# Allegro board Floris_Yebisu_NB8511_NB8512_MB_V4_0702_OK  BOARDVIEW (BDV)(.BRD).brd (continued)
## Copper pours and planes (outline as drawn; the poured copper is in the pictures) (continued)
+VCCSFR_OC on ART03: 61.36,76.32 56.29,76.32 56.23,76.26 55.01,76.26 54.63,75.87 52.81,75.87 52.81,75.87 52.34,75.87 52.33,75.86 50.38,75.86 50.24,75.71 50.24,74.7 50.41,74.53 52.9,74.53 52.92,74.55 56.26,74.55 57.05,75.35 61.35,75.35 61.62,75.61 61.62,76.07
+VCCSFR_OC on PWR04: 61.21,76.3 62.34,76.3 64.07,74.58 72.14,74.58 78.54,68.18 80.69,68.18 81.48,67.39 81.48,60.11 81.21,59.85 78.47,59.85 78.07,60.25 78.07,63.5 76.43,65.14 69.31,65.14 60.75,73.69 60.75,75.84
+VCCSFR_OC on ART05: 44.7,71.7 43.64,71.7 43.38,71.45 43.38,70.38 43.64,70.13 46.84,70.13 51.26,74.55 51.26,75.56 51.05,75.77 48.77,75.77
+VCCST on TOP: 108.51,36.35 107.96,36.35 107.68,36.07 107.68,33.76 103.35,29.43 88.17,29.43 86.48,27.73 82.27,27.73 81.35,26.81 81.35,26.44 81.39,26.39 86.67,26.39 88.82,28.54 104.36,28.54 104.8,28.98 105.56,28.98 105.66,28.88 105.66,28.17 105.81,28.01 105.81,27.45 105.87,27.4 107.19,27.4 107.34,27.56 107.34,28.37 107.69,28.72 108.41,28.72 108.46,28.67 108.46,28.27 108.51,28.22 108.81,28.22 108.86,28.27 108.86,30.1 108.8,30.16 108.8,36.06
+VCCST on BOTTOM: 108.71,35.94 109.11,35.54 109.11,34.47 109.01,34.37 109.01,34.36 108.22,34.36 108.01,34.57 108.01,36.11 108.2,36.29 108.46,36.29 108.61,36.14 108.61,36.04 108.71,35.94
+VCCST on BOTTOM: 51.26,66.37 51.26,65.86 51.76,65.35 52.12,65.35 52.22,65.45 52.22,66.34 52.14,66.42 51.66,66.42 51.61,66.47 51.36,66.47
+VCCST on ART05: 82.42,24.84 81.79,24.2 72.64,24.2 72.26,24.58 72.26,25.22 74.17,27.12 82.29,27.12 82.42,27
+VCCST on ART05: 52.68,66.27 52.68,63.47 50.75,61.54 49.73,61.54 49.43,61.85 49.43,63.22 49.63,63.42 49.63,63.93 49.62,63.94 49.62,64.6 51.74,66.72 52.22,66.72
+VCCSTG_IO on BOTTOM: 60.33,36.8 62.85,34.29 75.67,34.29 77.39,32.56 81.56,32.56 84.53,35.53 84.53,36.34 84.68,36.5 84.68,38.81 83.69,39.8 83.69,40.56 82.56,41.69 82.56,42.31 82.61,42.36 82.97,42.36 83.01,42.32 83.01,42 84.35,40.67 84.35,40.26 85.26,39.34 85.26,34.31 82.1,31.15 77.33,31.15 75.13,33.36 61.97,33.36 59.18,36.14 59.18,36.5 59.48,36.8
+VCCSTG_OUT_FUSE on TOP: 106.81,58.19 107.45,58.19 107.45,58.19 107.88,58.19 108.18,57.89 108.18,57.69 108.27,57.6 109.26,57.6 109.29,57.63 109.29,57.98 109.1,58.17 108.73,58.17 108.15,58.75 106.81,58.75
+VDD on TOP: 147.49,63.95 148.13,64.59 148.89,64.59 148.99,64.69 148.99,65.05 148.94,65.1 146.18,65.1 145.97,65.3 145.29,65.3 145.01,65.58 144.42,65.58 144.37,65.53 144.37,64.06 144.48,63.95
+VDDQ_CPU on TOP: 101.51,59.08 104.25,59.08 104.74,59.57 105.13,59.57 105.26,59.45 105.46,59.45 105.95,59.93 109.52,59.93 109.68,59.78 110.42,59.78 110.48,59.84 110.48,60.31 110.05,60.74 110.05,66.32 111.16,67.42 111.16,71.79 111.12,71.83 111.12,74.88 111,75 84.96,75 81.02,71.07 81.02,67.38 81.04,67.37 81.04,60.2 81.04,60.2 81.04,59.74 81.12,59.66 84.18,59.66 86.23,57.6 100.03,57.6 ; 5 cut-outs
+VDDQ_CPU on BOTTOM: 99.02,57.68 100.18,57.68 100.3,57.8 100.3,58.38 100.4,58.48 101.27,58.48 102.16,59.37 102.16,59.74 101.9,60 87.65,60 86.54,61.11 85.35,61.11 84.33,60.09 84.33,59.51 84.62,59.22 84.62,58.5 84.75,58.37 98.33,58.37
+VDDQ_LP4X on BOTTOM: 45.97,75.77 45.87,75.66 45.87,72.62 45.92,72.57 46.94,72.57 47.34,72.97 48.66,72.97 49.27,73.58 49.27,75.05 48.97,75.36 47.29,75.36 46.89,75.77
+VDDQ_LP4X on GND02: 61.47,90.88 61.47,92.47 62.93,93.93 123.57,93.93 128.27,89.23 128.27,79.58 127.35,78.66 122.58,78.66 119.17,75.26 99.82,75.26 99.06,76.02 65.33,76.02 61.47,79.88 61.47,81.99 62.23,82.75 64.51,82.75 65.15,82.12 68.45,82.12 68.96,82.62 70.48,82.62 71.12,81.99 79.63,81.99 80.52,82.88 82.42,82.88 83.06,82.24 86.74,82.24 87.25,82.75 88.14,82.75 89.15,81.73 97.15,81.73 98.68,83.26 99.06,83.26 99.95,82.37 104.65,82.37 105.15,82.88 106.55,82.88 107.69,81.73 114.43,81.73 115.44,82.75 123.19,82.75 123.7,82.24 125.73,82.24 126.11,82.62 126.11,89.23 124.84,90.5 123.95,90.5 123.32,89.86 114.81,89.86 114.17,90.5 105.92,90.5 105.41,89.99 98.04,89.99 97.41,90.62 89.3,90.62 88.67,89.99 83.21,89.99 83.06,89.84 82.29,89.84 82.14,89.99 80.77,89.99 80.14,90.62 71.37,90.62 70.74,89.99 63.37,89.99 62.74,90.62 61.72,90.62
+VDDQ_LP4X on PWR04: 52.19,74.34 52.19,81.17 57.83,86.81 60.17,86.81 62.43,89.08 63.02,89.08 63.37,88.72 67.08,88.72 67.44,89.08 80.77,89.08 81.13,88.72 84.53,88.72 84.89,89.08 125.01,89.08 125.33,89.4 125.33,92.58 123.59,94.32 62.55,94.32 59.35,91.13 53.61,91.13 47.47,84.98 47.47,76.97 47.46,76.97 47.46,75.38 47.14,75.05 47.14,74.6 47.8,73.94 51.78,73.94
+VDDQ_TX on BOTTOM: 43.28,77.65 42.57,76.93 42.57,74.65 43.08,74.14 45.16,74.14 45.21,74.19 45.21,75.46 44.7,75.97 44.7,77.54 44.6,77.65
AGND_CHG on TOP: 40.89,15.82 43.05,15.82 44.96,13.92 44.96,12.65 45.34,12.27 49.27,12.27 50.04,13.03 50.04,15.77 50.44,16.18 51.05,16.18 52.07,15.16 52.07,10.87 51.05,9.85 49.68,9.85 49.45,10.08 45.95,10.08 45.21,9.34 42.17,9.34 41.91,9.6 41.91,12.02 42.67,12.77 42.67,13.44 40.82,15.29 40.82,15.75
GND on ART05 (solid shape): 81.02,0.58 81.02,0.33 80.97,0.27 80.89,0.26 80.8,0.26 78.84,0.26 78.65,0.35 78.6,0.56 78.61,0.58 78.65,1.18 76.34,2.98 74.7,0.56 74.65,0.35 74.46,0.26 72.66,0.26 72.38,0.31 72.14,0.47 71.72,0.89 71.32,1.16 70.84,1.26 69.3,1.26 69.21,1.34 69.21,1.72 70.87,3.38 78.22,3.38
GND on TOP: 101.95,50.68 101.95,49.45 102.37,49.03 102.38,49.03 102.47,48.93 103.27,48.93 103.28,48.94 103.28,50.66 103.14,50.8 102.07,50.8 ; 3 cut-outs
GND on TOP: 154.13,14.25 154.94,14.25 154.94,11.63 154.81,11.5 153.92,11.5 153.8,11.63 153.8,11.73 153.82,11.76 153.82,12.42 154.02,12.62 154.02,14.15
GND on TOP: 20.7,72.08 21.72,72.08 21.84,72.21 21.84,73.63 21.74,73.73 20.62,73.73 20.57,73.68 20.57,72.21
GND on TOP: 101.44,35.33 97.62,35.33 97.3,35 97.3,29.73 97.4,29.62 101.3,29.62 101.58,29.91 101.58,35.19
GND on TOP: 99.03,57.35 100.17,57.35 100.47,57.65 100.91,57.65 101.21,57.35 106.44,57.35 106.64,57.55 106.64,57.95 106.73,58.05 107.84,58.05 107.97,57.92 107.97,57.49 108.11,57.35 109.55,57.35 110.12,57.92 110.12,58.18 111.25,59.31 111.25,60.63 111.57,60.94 125.2,60.94 125.49,60.65 125.49,56.76 125.33,56.6 108.14,56.6 108.03,56.72 101.59,56.72 101.37,56.49 101.37,55.98 101.32,55.93 98.62,55.93 98.5,56.05 98.5,56.82
GND on TOP: 44.88,19.76 45.36,19.28 46.28,19.28 47.17,20.17 47.17,20.38 47.22,20.43 47.22,24.14 47.15,24.21 45.94,24.21 45.31,23.58 45.31,22.48 44.88,22.04
GND on TOP: 174.24,50.24 173.99,49.98 173.99,46.3 173.86,46.17 163.01,46.17 160.65,48.52 160.65,51 162.68,53.03 174.12,53.03 174.24,52.91
GND on TOP: 34.97,42.14 37.67,42.14 37.75,42.06 37.75,39.34 37.54,39.12 34.91,39.12 34.81,39.22 34.81,41.99
GND on TOP: 85.64,24.51 88.7,24.51 88.9,24.31 88.9,22.25 88.76,22.12 85.81,22.12 85.49,22.43 85.49,24.37
GND on TOP: 15.46,12.76 15.16,12.46 13.62,12.46 13.05,13.03 11.17,13.03 11.05,12.9 10.41,12.9 9.9,13.41 9.9,14.17 10.07,14.33 12.79,14.33 12.79,14.33 15.33,14.33 15.46,14.2
GND on TOP: outline of 232 points within 0.25,0.26 82.65,74.54
GND on TOP: 33.81,58.24 36.62,58.24 36.87,58.48 36.87,60.61 36.7,60.78 31.37,60.78 31.24,60.65 31.24,57.46 31.47,57.23 32.81,57.23
GND on TOP: 123.86,15.44 124.96,15.44 125.12,15.29 125.12,13.3 124.89,13.08 123.96,13.08 123.85,13.19 123.85,15.43
GND on TOP: 37.59,52.14 37.72,52.02 37.72,49.6 37.46,49.35 33.15,49.35 33.02,49.48 33.02,52.02 33.15,52.14
GND on TOP: 18.55,49.86 17.4,49.86 17.27,49.73 17.27,48.33 17.4,48.21 18.54,48.21 18.61,48.27 18.61,49.8
GND on TOP: 13.93,74.06 15.23,74.06 15.42,73.87 15.42,70.39 15.38,70.36 15,70.36 14.63,70.74 14.63,70.74 14.07,71.3 14.07,71.84 13.8,72.11 13.8,73.93
GND on TOP: 168.1,32.79 168.24,32.65 168.24,31.2 168.19,31.16 167.72,31.16 167.63,31.25 166.11,31.25 166.01,31.35 166.01,32.18 165.66,32.53 164.84,32.53 164.54,32.84 164.54,35.58 165.35,36.4 167.18,36.4 168.1,35.48
GND on TOP: 24.56,7.59 24.61,7.54 25.04,7.54 25.19,7.39 29.67,7.39 29.77,7.49 29.77,8.4 29,9.17 29,10.03 29.06,10.08 29.46,10.08 29.56,10.18 29.56,11.05 29.67,11.15 30.22,11.15 30.27,11.2 30.27,11.81 30.12,11.96 23.62,11.96 23.49,11.83 23.49,10.61 23.32,10.44 23.32,10.03 23.47,9.88 23.67,9.88 24.56,8.99
GND on TOP: 136.33,59.89 133.73,59.89 133.6,60.02 133.6,60.65 133.73,60.78 134.75,60.78 135.14,61.17 135.14,64.22 135.38,64.46 135.38,65.48 135.51,65.61 137.54,65.61 137.81,65.34 137.81,61.37
GND on TOP: 65.28,44.14 62.9,44.14 62.83,44.06 62.83,40.68 63.14,40.37 64.45,40.37 65.37,41.29 65.37,44.06
GND on TOP: 16.97,7.74 16.97,6.63 17.07,6.53 19.51,6.53 19.56,6.58 19.56,7.74 19.3,8 17.22,8
GND on TOP: 180.97,38.47 181.76,38.47 182.04,38.19 182.04,35.56 181.13,34.66 178.86,34.66 178.71,34.8 178.71,34.81 178.53,34.99 178.53,36.22 178.62,36.3 180.32,36.3 180.56,36.55 180.56,38.06
GND on TOP: 182.92,25.68 183.33,26.08 185.88,26.08 186.08,25.88 186.08,24.58 185.55,24.05 179.93,24.05 179.88,24.1 179.88,25.65 179.91,25.68
GND on TOP: 20.11,12.21 18.29,12.21 17.88,11.81 16.86,11.81 16.76,11.71 16.76,10.64 18.74,8.66 19.91,8.66 20.01,8.76 20.01,11.45 20.37,11.81 21.59,11.81 21.64,11.86 21.64,12.11 21.59,12.16 20.17,12.16
GND on TOP: 142.81,66.82 142.01,66.02 142.01,65.74 142.3,65.45 143.01,65.45 143.58,64.87 144.04,64.87 144.12,64.95 144.12,65.5 144.37,65.76 145.06,65.76 145.37,65.45 146.08,65.45 146.3,65.22 149.56,65.22 149.6,65.27 149.6,65.55 149.42,65.73 148.84,65.73 148.58,66 148.58,66.14 147.64,67.07 147.61,67.11 147.61,67.28 147.35,67.53 146.24,67.53 146.21,67.51 145.1,67.51 145.08,67.49 145.08,66.93 144.98,66.82
GND on TOP: 141.07,35.79 138.07,35.79 137.67,35.38 137.31,35.38 137.16,35.23 137.16,34.77 137.21,34.72 139.14,34.72 139.29,34.87 141.73,34.87 143.97,37.11 144.88,37.11 145.03,37.26 145.03,37.61 144.78,37.87 143.15,37.87
GND on TOP: 45.85,15.82 48.64,15.82 48.89,15.57 48.89,13.03 48.59,12.72 45.9,12.72 45.72,12.9 45.72,15.69
GND on TOP: 73.35,22.11 75.05,22.11 75.17,21.99 75.17,19.09 74.92,18.84 73.23,18.84 73.14,18.93 73.14,21.9
GND on TOP: 139.48,66.88 141.22,66.88 142.34,67.99 143.05,67.99 144.02,68.96 144.02,69.47 143.97,69.52 142.95,69.52 142.34,68.91 139.95,68.91 139.29,68.25 139.29,67.06
GND on TOP: 45.72,63.47 45.72,61.54 45.97,61.29 46.53,61.29 46.63,61.39 46.63,61.74 46.89,62 46.89,65.35 46.63,65.61 46.63,68.91 46.53,69.01 45.01,69.01 44.85,68.86 44.85,64.34
GND on TOP: 48,47.7 52.83,47.7 52.96,47.83 52.96,49.6 52.83,49.73 48,49.73 47.88,49.6 47.88,47.83
GND on TOP: 53.44,55.45 53.85,55.85 53.85,57.22 53.72,57.35 48.13,57.35 48,57.22 48,55.57 48.13,55.45
GND on TOP: 26.82,33.4 24.99,33.4 24.97,33.37 24.97,32.64 25.8,31.8 27.15,31.8 27.81,32.46 27.81,33.09 27.68,33.22 27,33.22
GND on TOP: outline of 225 points within 0.25,0.26 191.4,97.75 ; 1 cut-out
GND on TOP: 71.79,55.56 72.07,55.28 72.07,53.35 72.03,53.31 71.65,53.31 71.55,53.41 71.55,53.82 71.47,53.9 71.07,53.9 71.04,53.92 71.04,54.4 70.99,54.46 70.17,54.46 70.06,54.56 70.06,54.76 70.16,54.86 70.53,54.86 70.85,55.18 70.85,55.32 71.09,55.56
GND on TOP: 137.95,50.09 138.31,49.72 139.05,49.72 139.06,49.73 141.1,49.73 141.22,49.6 141.22,48.97 141.1,48.84 139.06,48.84 139.01,48.9 136.39,48.9 136.09,49.2 136.09,49.71 136.47,50.09
GND on TOP: 17.91,46.23 17.63,45.95 17.63,41.93 18.18,41.37 23.34,41.37 23.37,41.35 25.14,41.35 25.27,41.48 25.27,42.11 25.12,42.26 24.1,42.26 23.82,42.54 23.82,45.08 22.96,45.95 22.35,45.95 21.83,45.43 19.16,45.43 18.36,46.23
GND on TOP: 86.99,46.94 87.12,46.81 88.95,46.81 89.17,46.59 90.03,46.59 90.06,46.62 90.06,48.17 90,48.23 87.1,48.23 86.99,48.13
GND on TOP: 108.39,49.1 109.4,49.1 111,47.5 111,45.06 110.84,44.9 108.2,44.9 105.59,47.52 105.59,47.98 105.79,48.18 105.79,49.42 105.86,49.49 108,49.49
GND on TOP: 26.82,28.52 29.77,28.52 29.97,28.72 34.85,28.72 35.1,28.47 35.1,27 34.59,26.49 34.59,25.37 35.05,24.91 36.07,24.91 36.22,25.07 36.22,29.64 34.8,31.06 29.67,31.06 29.11,30.5 26.54,30.5 26.29,30.25 26.29,29.06 26.11,28.88 26.11,28.37 26.16,28.32 26.62,28.32
GND on TOP: 92.98,46.58 95.48,46.58 95.61,46.45 95.61,44.77 95.71,44.67 96.82,44.67 96.89,44.6 96.89,43.5 96.82,43.44 95.18,43.44 95.06,43.31 95.06,42.7 94.98,42.62 93.53,42.62 93.47,42.69 93.47,43.33 93.29,43.51 93.29,44.1 93.04,44.35 93.04,45.43 92.92,45.56 92.92,46.52
GND on TOP: 22.99,74.24 23.75,74.24 23.87,74.11 23.87,73.48 24.13,73.23 24.92,73.23 25.58,72.57 25.58,72 25.41,71.83 23.37,71.83 22.99,72.21
GND on TOP: 156.69,78.81 154.94,78.81 154.8,78.67 154.8,77.54 154.69,77.44 154.41,77.44 154.18,77.67 153.67,77.67 153.29,78.05 151.33,78.05 151.11,78.27 151.11,81.38 151.92,82.19 156.13,82.19 157.73,80.59 157.73,79.86
GND on TOP: 116.39,12.47 116.28,12.36 114.65,12.36 114.29,12.72 114.29,14.71 114.45,14.87 116.35,14.87 116.39,14.84
GND on TOP: 14.48,77.8 15.11,77.8 15.12,77.79 15.12,76.9 15.21,76.81 15.21,76.5 15.12,76.4 13.59,76.4 13.59,76.91
GND on TOP: 101.09,48.46 95.74,48.46 95.56,48.27 95.56,47.29 95.75,47.1 97.6,47.1 97.79,46.91 99.06,46.91 99.45,47.3 99.47,47.29 99.72,47.29 99.74,47.29 100.17,46.86 100.84,46.86 100.94,46.76 101.14,46.76 101.17,46.78 101.17,48.38 ; 2 cut-outs
GND on TOP: 84.86,30.65 85.93,29.59 87.92,29.59 87.98,29.65 87.98,34.38 87.94,34.42 84.97,34.42 84.86,34.3
GND on TOP: 81.08,43.02 80.57,43.53 79.66,43.53 79.58,43.45 79.58,42.67 79.51,42.6 78.86,42.6 78.82,42.64 78.82,44.19 78.72,44.29 76.88,44.29 76.87,44.29 76.87,45.59 77.36,46.08 77.36,47.37 77.38,47.39 78.16,47.39 78.36,47.19 78.36,46.39 78.4,46.35 78.77,45.97 79.84,45.97 80.18,45.63 80.71,45.63 80.96,45.88 81,45.92 81,46.58 81.16,46.74 81.16,47.52 81.23,47.6 82.75,47.6 82.82,47.53 82.82,46.08 82.72,45.99 82.58,45.99 82.38,45.78 82.38,45.57 82.51,45.44 82.51,45.28 82.59,45.2 82.66,45.26 83.95,45.26 84.38,45.69 85.9,45.69 86.07,45.52 86.07,43.97 85.74,43.65 85.74,42.72 85.7,42.67 85.07,42.67 85.02,42.72 85.02,43.34 84.85,43.51 83.96,43.51 83.86,43.41 83.86,43.04 83.79,42.96 82.81,42.96 82.74,43.02
GND on TOP: 126.42,47.6 128.39,47.6 128.63,47.36 128.63,43.09 128.56,43.02 126.4,43.02 126.35,43.06 126.35,47.53
GND on TOP: 79.75,57.35 79.88,57.22 79.88,56.59 79.75,56.46 77.47,56.46 77.34,56.59 77.34,57.22 77.47,57.35
GND on TOP: 175.11,9.07 176.02,9.07 176.17,9.22 176.17,10.54 175.82,10.89 174.45,10.89 174.24,10.69 174.24,9.93
GND on TOP: 69.93,49.22 69.01,49.22 68.77,48.98 68.77,48.77 68.53,48.53 68.46,48.53 68.39,48.47 68.39,46.87 68.25,46.73 66.76,46.73 66.71,46.69 66.71,45.96 67.27,45.4 67.27,43.52 68.27,42.52 69.81,42.52 69.92,42.63 69.92,43.86 69.62,44.15 69.62,46.12 69.96,46.46 69.96,49.19
GND on TOP: 150.42,40.31 150.42,43.86 150.72,44.17 155.66,44.17 156.17,44.68 159.2,44.68 159.39,44.49 159.39,39.55 159.24,39.39 159.24,39.39 159.09,39.25 154.78,39.25 153.82,40.21 150.52,40.21
GND on TOP: 144.14,75.64 144.91,74.88 144.91,74.5 144.78,74.37 144.52,74.37 144.27,74.62 138.56,74.62 138.17,74.24 132.74,74.24 132.59,74.39 132.59,75.99 132.74,76.15 144.02,76.15 144.14,76.02
GND on TOP: 180.1,52.86 182.45,52.86 182.46,52.85 187.2,52.85 187.3,52.75 187.3,45.08 186.99,44.78 185.62,44.78 185.21,44.37 185.21,43.56 185.11,43.46 184.71,43.46 184.55,43.3 184,43.3 183.94,43.25 183.94,42.85 184.05,42.75 185.01,42.75 185.21,42.54 185.21,41.48 185.16,41.42 183.28,41.42 183.08,41.22 183.08,40.61 183.18,40.51 183.49,40.51 183.74,40.26 183.74,39.95 183.64,39.85 182.88,39.85 179.68,43.05 179.68,52.43
GND on BOTTOM: 175.66,75.3 181.05,75.3 181.92,76.17 186.77,76.17 186.96,75.98 186.96,73.95 186.77,73.76 181.49,73.76 180.58,74.66 175.66,74.66 175.6,74.73 175.6,75.23
GND on BOTTOM: 73.14,18.97 73.26,18.85 75.03,18.85 75.18,19 75.18,21.94 75.08,22.04 73.28,22.04 73.14,21.9
GND on BOTTOM: 98.76,57.29 100.14,57.29 100.49,57.64 100.69,57.64 100.69,57.64 100.98,57.64 101.33,57.29 105.47,57.29 105.65,57.11 105.65,56.74 105.48,56.56 101.17,56.56 100.26,55.65 100.26,51.76 100.47,51.55 102.55,51.55 102.7,51.4 102.7,49.59 102.45,49.34 99.02,49.34 98.6,49.76 98.6,57.12
GND on BOTTOM: 39.62,64.39 39.67,64.44 42.52,64.44 42.97,63.98 42.97,63.27 42.92,63.22 42.16,63.22 42.06,63.32 41.04,63.32 40.89,63.47 39.83,63.47 39.62,63.68
GND on BOTTOM: 35.94,60.65 35.94,59.24 36.16,59.02 36.16,58.32 36.08,58.24 33.65,58.24 33.27,57.86 33.27,57.48 32.99,57.2 31.32,57.2 31.11,57.4 31.11,59.13 31.75,59.76 31.75,60.65 31.88,60.78 35.81,60.78
GND on BOTTOM: 38.89,38.96 38.81,38.88 34.19,38.88 34.06,39.01 34.06,42.06 34.4,42.4 38.75,42.4 38.89,42.26
GND on BOTTOM: 41.15,43.76 44.07,43.76 44.19,43.63 44.19,43.13 44.07,43 43.69,43 43.18,42.49 42.16,42.49 42.04,42.62 41.15,42.62 41.02,42.75 41.02,43.63
GND on BOTTOM: 55.48,14.94 54.36,14.94 54.34,14.92 54,14.92 53.12,14.04 53.12,13 53.85,12.28 55.34,12.28 55.49,12.43 55.49,14.93
GND on BOTTOM: 133.73,64.08 136.4,64.08 136.65,64.34 137.92,64.34 138.17,64.08 138.17,62.68 138.05,62.56 136.65,62.56 136.27,62.94 134.87,62.94 134.49,62.56 133.98,62.56 133.6,62.94 133.6,63.95
GND on BOTTOM: 82.63,24.65 88.52,24.65 88.73,24.44 88.73,22.26 88.59,22.12 85.92,22.12 85.13,22.91 82.65,22.91 82.51,23.05 82.51,24.53
GND on BOTTOM: 170.18,51.89 170.59,51.89 170.63,51.86 170.63,50.8 170.44,50.61 169.59,50.61 169.49,50.71 169.49,51.06 170.14,51.71 170.14,51.85
GND on BOTTOM: 38.12,79.07 38.73,78.46 38.73,76.4 38.61,76.27 36.45,76.27 36.32,76.4 36.32,78.94 36.45,79.07
GND on BOTTOM: 172.87,51.94 174.09,51.94 174.28,51.75 174.28,50.25 174.09,50.06 174.09,48.99 173.89,48.79 173.07,48.79 172.51,49.35 172.51,51.58
GND on BOTTOM: 129.08,87.75 129.44,87.75 129.54,87.86 129.54,88.52 129.69,88.67 129.69,89.13 129.64,89.18 129.33,89.18 129.13,88.97 128.42,88.97 128.27,88.82 128.27,87.75 128.42,87.6 128.93,87.6
GND on BOTTOM: 179.68,48.79 179.68,51.94 179.93,52.19 180.95,52.19 181.15,51.99 181.15,48.74 181.1,48.69 179.78,48.69
GND on BOTTOM: 43.74,80.85 43.53,81.05 42.88,81.05 42.88,81.04 41.91,82.01 41.91,82.93 42.14,83.16 42.85,83.16 43.89,82.12 43.89,81.66 44.04,81.51 47.8,81.51 48.18,81.89 48.18,83.21 48.17,83.22 48.17,88.05 47.7,88.52 47.7,91.67 48,91.97 50.24,91.97 50.34,91.87 50.34,88.29 49.5,87.45 49.5,82.24 48.26,81 46.33,81 46.25,80.92 45.06,80.92 44.98,80.85
GND on BOTTOM: 22.46,63.08 21.99,62.61 18.95,62.61 18.44,63.12 17.93,63.12 17.88,63.07 17.88,62.66 17.88,62.66 17.88,61.23 17.97,61.14 18.64,61.14 19.15,60.63 22.38,60.63 22.6,60.86 22.6,62.15 22.86,62.41 23.24,62.41 23.37,62.53 23.37,63.14 23.82,63.6 23.82,65.5 23.72,65.61 22.81,65.61 22.46,65.26
GND on BOTTOM: 50.95,1.03 50.86,0.97 50.78,0.89 50.36,0.47 50.12,0.31 49.84,0.26 37.28,0.26 37.21,0.33 37.21,0.58 39.44,2.82 41.3,2.82 41.65,3.17 41.65,4.44 42.26,5.05 50.95,5.05 50.95,5.05
GND on BOTTOM: 53.85,56.21 53.85,57.02 53.52,57.35 48.13,57.35 48,57.22 48,55.46 48.03,55.44 53.07,55.44
GND on BOTTOM: 27.63,46.71 27.63,45.39 28.04,44.98 28.9,44.98 29.06,45.13 29.06,46.76 28.9,46.91 27.84,46.91
GND on BOTTOM: 77.33,6.59 75.31,8.61 75.31,9.62 75.32,9.63 75.32,11.5 75.33,11.51 77.44,11.51 77.59,11.36 77.59,9 78.43,8.15 87.91,8.15 88.07,7.99 88.07,5.29 87.94,5.15 83.8,5.15 82.37,6.59
GND on BOTTOM: 18.74,9.73 16,9.73 15.85,9.57 15.85,6.83 16.1,6.58 19,6.58 19.15,6.73 19.15,7.59 18.74,8
GND on BOTTOM: 134.41,92.63 134.41,92.12 134.72,91.82 134.72,91.01 134.77,90.95 135.38,90.95 135.84,91.41 135.84,91.77 136.19,92.12 136.19,92.58 136.04,92.73 134.52,92.73
GND on BOTTOM: 40.23,59.75 41.34,59.75 41.36,59.72 41.36,59.62 41.45,59.53 41.45,59.43 41.73,59.14 41.73,59.08 41.62,58.96 39.87,58.96 39.78,59.06 39.78,59.25 39.87,59.34 40.2,59.34 40.22,59.37 40.22,59.74
GND on BOTTOM: 134.68,43.88 129.93,43.88 129.6,43.54 129.6,36.16 129.76,36 134.48,36 134.8,36.32 134.8,43.76
GND on BOTTOM: 162.99,35.46 164.59,35.46 164.69,35.35 164.69,34.61 164.88,34.43 165.85,34.43 166.39,34.97 166.88,34.97 167.08,34.77 167.08,34.39 165.13,32.44 163.07,32.44 162.85,32.65 162.85,35.32
GND on BOTTOM: 87.96,33.28 86.55,33.28 84.85,31.58 84.85,30.62 85.65,29.82 85.65,28.87 85.81,28.71 85.81,28.71 87.91,28.71 88.04,28.84 88.04,33.21
GND on BOTTOM: 175.77,57.35 178.69,57.35 179.07,56.97 179.07,54.94 178.94,54.81 175.26,54.81 175.13,54.94 175.13,56.72
GND on BOTTOM: 136.56,21.7 136.71,21.55 137.97,21.55 138.53,20.99 138.53,18.41 138.06,17.94 135.16,17.94 135.13,17.97 135.13,21.75 134.27,22.62 134.27,23.74 133.71,24.3 133.71,24.42 133.88,24.59 133.88,27.13 133.23,27.78 132.4,27.78 130.32,29.86 130.32,34.92 130.47,35.07 133.31,35.07 135.67,32.71 137.92,32.71 138.68,31.95 138.68,28.78 136.56,26.65
GND on BOTTOM: 112.17,33.76 110.74,32.33 110.74,27.81 110.84,27.71 113.79,27.71 113.93,27.85 113.93,33.56 113.73,33.76
GND on BOTTOM: 45.82,62.2 45.92,62.1 45.92,61.49 46.12,61.29 46.68,61.29 46.84,61.44 46.84,61.49 47.75,62.41 47.75,64.49 47.6,64.64 46.02,64.64 45.82,64.44
GND on BOTTOM: 42.67,67.43 42.67,66.93 42.87,66.72 45.16,66.72 45.26,66.62 47.34,66.62 47.7,66.98 47.7,67.94 47.55,68.09 46.12,68.09 44.8,69.42 43.58,69.42 43.38,69.21 43.38,68.15
GND on BOTTOM: 170.64,30.45 175.46,30.45 175.77,30.15 175.77,26.39 174.9,25.52 170.28,25.52 169.82,25.98 169.82,29.64
GND on BOTTOM: 13.84,76.4 14.6,76.4 14.98,76.78 14.98,80.72 14.73,80.97 9.65,80.97 9.4,80.72 9.4,79.96 9.65,79.7 13.21,79.7 13.46,79.45 13.46,76.78
GND on BOTTOM: 103.85,15.39 105.96,15.39 106.55,14.8 107.15,14.8 107.66,14.28 107.66,11.79 107.61,11.74 107.61,10.47 105.26,8.11 102.12,8.11 101.97,8.26 101.97,9.89 103.62,11.55 103.62,15.16
GND on BOTTOM: 150.92,42.29 151.84,43.2 151.84,43.81 151.89,43.86 155.65,43.86 156.41,44.63 158.06,44.63 158.23,44.46 158.23,39.24 158.2,39.21 156.55,39.21 156.51,39.25 156.51,40.71 156.26,40.97 155.55,40.97 155.29,41.22 154.07,41.22 153.92,41.07 153.92,40.31 153.82,40.21 150.62,40.21 150.26,40.56 150.26,42.24 150.32,42.29
GND on BOTTOM: 101.56,35.05 101.56,29.46 101.46,29.35 97.71,29.35 97.33,29.73 97.33,35.14 97.46,35.26 101.35,35.26
GND on BOTTOM: outline of 276 points within 0.25,0.26 191.4,97.75
GND on BOTTOM: 138.05,74.24 138.56,74.75 138.56,78.56 138.36,78.75 137.02,78.75 136.7,79.07 135,79.07 134.87,78.94 134.87,74.37 135,74.24
GND on BOTTOM: 64.77,42.87 63.12,42.87 62.64,42.39 62.64,40.44 62.93,40.14 64.33,40.14 64.51,40.33 64.51,41.35 65.15,41.98 65.15,42.11 64.9,42.36 64.9,42.75
GND on BOTTOM: 35.3,51.38 35.18,51.51 35.18,52.27 35.3,52.4 37.72,52.4 37.84,52.27 37.84,51.51 37.72,51.38
GND on BOTTOM: 176.49,34.3 175.92,34.87 175.92,35.33 176.07,35.48 176.07,36.4 176.12,36.45 176.68,36.45 176.73,36.4 176.73,35.43 176.81,35.35 177.76,35.35 178.24,35.83 178.24,36.05 178.48,36.29 180.24,36.29 180.57,36.62 180.57,38.18 180.84,38.46 181.78,38.46 182.02,38.22 182.02,35.49 180.83,34.3
GND on BOTTOM: 126.49,47.32 128.52,47.32 128.78,47.06 128.78,43.13 128.65,43 126.49,43 126.36,43.13 126.36,47.19
GND on BOTTOM: 44.55,89.48 44.3,89.23 44.3,86.89 44.65,86.54 45.97,86.54 46.23,86.79 46.23,89.23 45.97,89.48
GND on BOTTOM: 103.5,23.33 106.15,23.33 106.32,23.16 106.32,20.8 106.06,20.55 103.51,20.55 103.29,20.76 103.29,23.13
GND on BOTTOM: 15.86,0.26 15.33,0.47 15.11,1 15.11,2 14.75,2.89 13.86,3.26 3,3.26 2.47,3.47 2.25,4 2.25,12.26 1.95,13.01 0.67,13.53 0.45,14.06 0.45,24.2 0.67,24.73 1.95,25.26 2.25,26 2.25,29.45 12.7,29.45 13.43,29.06 13.95,29.7 13.95,32.03 14.41,31.57 17.93,31.57 19.32,30.18 25.02,30.18 25.26,30.43 28.02,30.43 29,29.44 29,28.47 28.9,28.37 28.55,28.37 28.14,28.78 25.27,28.78 25.21,28.72 25.21,28.03 25.01,27.83 24.02,27.83 23.87,27.69 23.87,27.25 23.75,27.12 19.91,27.12 16.57,23.79 15.05,23.79 14.45,24.38 10.59,24.38 8.78,22.56 6.75,22.56 6.54,22.34 6.54,16.8 6.98,16.35 8.47,16.35 8.75,16.07 8.75,14.9 6.81,12.96 6.81,9.18 8.11,7.89 9.47,7.89 10.79,6.57 10.79,5.02 11.5,4.3 14.99,4.3 16.86,2.43 16.86,0.26
GND on BOTTOM: 109.82,50.86 109.54,50.86 109.44,50.76 109.44,50.45 109.6,50.29 109.6,49.74 109.37,49.5 108.81,49.5 108.64,49.67 108.64,49.83 108.12,50.35 108.01,50.35 106.85,49.18 106.85,48.16 106.7,48.01 106.7,47.7 107.19,47.21 107.57,47.21 107.94,47.59 108.68,47.59 108.92,47.34 108.92,47.2 109.48,46.64 112.94,46.64 113.37,47.07 113.37,49.34 112.33,50.38 110.3,50.38
GND on BOTTOM: 141.3,49.83 141.38,49.75 141.38,48.92 141.27,48.81 135.88,48.81 135.7,48.99 135.7,49.7 135.83,49.83
GND on BOTTOM: 45.77,24.41 45.36,24 45.36,22.78 44.91,22.32 44.91,20.6 45.12,20.38 47.17,20.38 47.22,20.43 47.22,24.33 47.14,24.41
GND on BOTTOM: 33.65,50.87 34.8,50.87 35.53,50.14 36.16,50.14 36.32,49.97 36.32,49.48 36.19,49.35 33.65,49.35 33.53,49.48 33.53,50.75
GND on BOTTOM: 50.62,49.73 48,49.73 47.88,49.6 52.21,47.72 52.32,47.83 52.32,48.49 52.12,48.69 51.66,48.69
GND on BOTTOM: 33.21,28.39 33.4,28.58 33.4,29.46 33.53,29.59 33.53,30.76 33.45,30.83 31.14,30.83 30.99,30.68 30.99,28.52 31.11,28.39
GND on BOTTOM: 130.43,82 130.34,81.92 130.34,80.5 130.66,80.18 131.96,80.18 131.97,80.18 132.19,80.18 132.36,80.36 132.36,81.8 132.16,82
GND on BOTTOM: 96.2,15.69 96.4,15.49 98.1,15.49 98.31,15.69 98.31,17.76 97.2,18.88 97.2,19.21 96.98,19.42 96.32,19.42 96.2,19.3
GND on BOTTOM: 119.22,57.22 114.02,57.22 113.87,57.07 113.87,56.63 113.98,56.53 116.25,56.53 116.94,55.83 125.2,55.83 125.44,56.07 125.44,57.85 125.26,58.02 123.39,58.02 123.17,58.24 120.24,58.24
GND on BOTTOM: 27.43,64.46 27.81,64.08 29.26,64.08 29.34,64.01 29.34,63.07 28.7,62.43 28.07,62.43 27.1,63.4 27.1,64.36 27.2,64.46
GND on BOTTOM: 75.61,29.77 74.65,29.77 73.89,30.53 73.31,30.53 73.29,30.55 73.29,32.08 73.69,32.48 74.98,32.48 76.1,31.37 76.1,30.45 75.69,30.05 75.69,29.84
GND on BOTTOM: 18.24,41.37 13.95,41.37 13.95,43.2 13.43,43.84 12.7,43.46 2.75,43.46 2.75,45.9 2.45,46.65 1.7,46.96 1.2,46.96 0.67,47.17 0.45,47.7 0.45,49.05 8.94,49.05 9.78,48.56 10.4,49.3 10.4,64.7 9.78,65.44 8.94,64.96 0.45,64.96 0.45,66 0.67,66.53 1.95,67.05 2.25,67.8 2.25,71.94 1.95,72.69 1.2,73 1,73 0.47,73.21 0.25,73.74 0.25,74.54 4.38,74.54 4.44,74.53 4.49,74.49 4.55,74.43 4.77,74.29 5.02,74.24 6.98,74.24 7.11,74.25 7.24,74.29 11.21,70.32 14.07,70.32 15.11,69.28 15.11,64.76 13.24,62.9 11.78,62.9 10.89,62.01 10.89,52.42 11.51,51.8 18.09,51.8 18.7,51.19 18.7,46.44 18.9,46.25 19.15,46.25 19.35,46.05 19.35,42.45 19.57,42.24 22.17,42.24 22.3,42.36 22.3,46.1 22.35,46.15 22.91,46.15 23.01,46.05 23.01,43.1 23.92,42.19 23.92,41.68 23.62,41.37
GND on BOTTOM: 21.58,55.97 26.54,55.97 27.15,55.35 27.15,51.73 25.5,50.08 22.29,50.08 22.2,50.17 22.2,51.57 21.33,52.45 21.33,55.72
GND on GND02: outline of 208 points within 0.25,0.26 191.4,97.75 ; 18 cut-outs
GND on ART03: 82.04,61.03 84.71,61.03 87.12,58.62 87.12,57.73 112.49,57.73 113.3,58.54 117.9,58.54 118.84,59.48 122.5,59.48 126.08,63.07 126.08,73.24 127.13,74.28 127.13,90 121.93,95.2 63.84,95.2 61.13,92.49 61.13,88.6 60.79,88.26 60.38,88.26 59.31,87.18 59.31,79.83 64.7,74.43 69.91,74.43 71.88,72.46 74.42,72.46 78.48,68.4 80.77,68.4 81.66,67.51 81.66,61.41
GND on ART03: 144.4,78.69 144.4,77.67 144.02,77.29 143.13,77.29 143,77.42 143,78.69 143.13,78.81 144.27,78.81
GND on ART03: 145.03,79.83 145.79,79.83 145.92,79.7 145.92,79.07 145.79,78.94 145.29,78.94 144.78,79.45 143.38,79.45 143.25,79.58 143.25,80.46 143.38,80.59 144.27,80.59
GND on ART03: outline of 106 points within 0.25,79.7 58.8,97.75
GND on ART03: 143.89,75.51 143.64,75.77 143.64,76.02 144.91,77.29 145.79,77.29 146.3,76.78 149.22,76.78 149.6,77.16 149.6,80.21 150.62,81.23 150.75,81.23 153.8,84.27 155.19,84.27 156.34,85.42 158.75,85.42 159.89,84.27 159.89,78.81 156.59,75.51
GND on ART03: outline of 301 points within 0.25,0.26 191.4,97.75
GND on ART03: 22.1,31.82 24.89,31.82 25.27,31.44 25.27,28.78 24.64,28.14 22.68,28.14 22.2,27.66 21.18,27.66 20.57,28.27 20.57,30.3
GND on ART03, PWR04, ART05: 105.92,23.64 103.38,23.64 103.07,23.34 103.07,20.55 103.38,20.24 105.87,20.24 106.12,20.5 106.12,23.44
GND on PWR04: outline of 423 points within 0.25,0.26 191.4,97.75 ; 1 cut-out
GND on ART05: 9.35,79.7 9.35,80.72 9.36,81.65 8.43,81.65 7.62,81.65 7.56,81.66 7.51,81.69 7.45,81.75 7.23,81.9 6.98,81.95 5.02,81.95 4.77,81.9 4.55,81.75 4.49,81.69 4.44,81.66 4.38,81.65 0.25,81.65 0.25,82.44 0.47,82.97 1,83.19 1.3,83.19 2.05,83.5 2.35,84.24 2.35,88.64 2.05,89.39 1.3,89.7 1,89.7 0.47,89.91 0.25,90.44 0.25,94.5 0.47,95.03 1,95.25 4.7,95.25 5.23,95.03 5.45,94.5 5.45,92.42 5.54,91.94 5.81,91.53 10.22,87.12 10.35,86.95 10.42,86.75 10.86,86.03 11.65,85.75 37.65,85.75 39.95,86.7 40.9,89 40.94,89.48 41.26,90.51 41.91,91.36 48,97 48.79,97.49 49.68,97.71 53.02,97.75 53.21,97.65 53.25,97.44 53.25,97.42 53.2,96.91 55.11,95.37 56.45,97.44 56.49,97.65 56.68,97.75 63.61,97.75 63.63,97.74 63.63,94.56 61.34,92.28 59.69,93.93 47.88,93.93 38.99,85.04 24,85.04 21.72,82.75 14.86,82.75 11.81,79.7
GND on ART05: 168.57,87.66 172.85,91.94 177.85,91.94 178.46,91.33 178.46,87.89 179,87.36 179,87.04 179.14,86.91 184.22,86.91 188.21,82.92 188.21,76.65 189.06,75.8 189.06,60.65 187.27,58.87 187.27,57.08 186.27,56.08 182.75,56.08 179.96,53.29 175.89,53.29 174.24,51.64 174.24,50.62 173.21,49.59 172.19,49.59 171.92,49.86 167.26,49.86 166.88,49.48 166.88,49.44 164.84,47.41 162.02,47.41 157.45,51.97 153.34,51.97 150.76,54.55 149,54.55 148.33,55.22 148.33,57.24 147.64,57.93 147.64,60.11 148.36,60.83 148.36,62.72 148.7,63.06 149.79,63.06 150.04,63.31 150.04,65.18 150.2,65.34 156.05,65.34 156.89,66.18 156.89,76.8 156.74,76.95 156.74,78.96 155.09,80.6 147.59,80.6 147.17,80.19 136.2,80.19 135.57,80.82 135.57,83.33 136.95,84.71 148.28,84.71 150.01,82.98 159.81,82.98 162.1,85.27 162.1,86.49 163.27,87.66
GND on ART05: outline of 131 points within 60.45,0.26 191.4,97.75
GND on ART05: outline of 145 points within 0.25,0.26 50.04,74.54
GND on ART06: outline of 362 points within 0.25,0.26 191.4,97.75
GND on ART06: 21.84,31.82 24.33,31.82 25.04,31.11 25.04,30.05 25.25,29.84 25.25,28.47 24.66,27.89 22.22,27.89 21.89,27.56 21.08,27.56 20.42,28.22 20.42,30.4
GND on ART06: 105.92,23.64 103.38,23.64 103.07,23.34 103.07,20.55 103.38,20.24 105.56,20.24 106.04,20.72 106.04,23.52
GND on GND07: outline of 202 points within 0.25,0.26 191.4,97.75 ; 16 cut-outs
PVIN_VPP on BOTTOM: 45.01,85.77 44.93,85.7 44.93,85.06 44.73,84.86 44.73,84.15 44.75,84.12 44.75,83.59 44.8,83.54 45.62,83.54 46.63,82.52 46.68,82.52 46.86,82.7 46.86,82.9 46.84,82.93 46.84,83.33 45.97,84.2 45.97,85.57 45.77,85.77
V1P2A_LX on BOTTOM: 32.64,62.43 32.76,62.3 32.76,61.16 32.64,61.03 31.88,61.03 31.62,61.29 29.21,61.29 29.08,61.41 29.08,62.3 29.21,62.43
V1P2A_PGOOD on BOTTOM: 33.25,65.39 33.68,65.39 33.7,65.37 33.7,63.64 33.68,63.62 33.11,63.62 33.09,63.63 33.09,64.8 33.24,64.95 33.24,65.38
V1P8A_LX on BOTTOM: 42.67,61.59 42.67,59.51 42.54,59.38 41.78,59.38 41.65,59.51 41.65,59.74 41.45,59.94 40.23,59.94 40.23,59.95 40.23,60.19 40.23,60.2 41.4,60.2 41.53,60.33 41.53,61.47 41.7,61.64 42.62,61.64
V3P3A_IN on TOP: 53.24,47.48 48.21,47.48 47.65,46.92 47.65,46.45 47.8,46.3 48.66,46.3 48.92,46.56 50.42,46.56 50.54,46.43 50.54,45.92 50.29,45.67 50.29,44.78 50.42,44.65 53.34,44.65 53.54,44.85 53.54,47.17
V3P3A_IN on BOTTOM: 52.43,45.49 50.97,45.49 50.67,45.79 50.67,46.43 50.11,46.99 49.12,46.99 49.07,46.94 49.07,46.43 49.02,46.38 47.91,46.38 47.78,46.51 47.78,47.16 48.1,47.48 52.37,47.48 52.63,47.23 52.63,45.69
V3P3A_LX on BOTTOM: 45.34,46.43 45.34,44.4 45.21,44.27 42.67,44.27 42.54,44.4 42.54,49.05 42.79,49.3 47.47,49.3 47.62,49.14 47.62,47.27 47.56,47.21 46.12,47.21
V3P3A_OUT on TOP: 37.59,48.69 37.59,42.78 37.47,42.65 35.06,42.65 34.92,42.79 34.92,48.71 35.1,48.89 37.39,48.89
V3P3A_OUT on BOTTOM: 39.62,48.78 39.21,49.19 36.41,49.19 36.32,49.1 34.16,49.1 33.91,48.84 33.91,43.23 34.54,42.59 39.45,42.59 39.62,42.76
VCCIN_AUX_PHASE on BOTTOM: 89.59,22.44 95.24,22.44 95.5,22.19 95.5,14.32 95.43,14.25 90.76,14.25 90.6,14.41 90.6,15.53 90.47,15.67 89.43,15.67 89.36,15.73 89.36,22.22
VCCIN_AUX_VIN on TOP: 85.64,21.94 88.65,21.94 88.79,21.8 88.79,19.71 88.64,19.56 85.72,19.56 85.5,19.78 85.5,21.79
VCCIN_AUX_VIN on BOTTOM: 81.44,21.94 88.65,21.94 88.79,21.8 88.79,14.37 88.58,14.16 83.73,14.16 83.53,14.35 83.53,15.82 81.33,18.03 81.33,21.83
VCCIN_PHASE1 on BOTTOM: 129.26,27.34 131.85,27.34 131.98,27.21 131.98,22.64 132.44,22.18 134,22.18 134.31,21.87 134.31,16.57 134.3,16.56 129.73,16.56 129.61,16.69 129.61,17.51 129.26,17.85 128.4,17.85 128.36,17.9 128.36,24.27 129.13,25.04 129.13,27.2
VCCIN_PHASE2 on BOTTOM: 110.78,21.59 110.78,16.84 110.89,16.73 115.59,16.73 115.69,16.83 115.69,20.43 116.01,20.75 119.86,20.75 119.91,20.8 119.91,21.98 119.91,21.98 119.91,22.48 117.73,24.66 117.21,24.66 116.89,24.98 116.89,27 116.67,27.23 113.75,27.23 113.74,27.22 112.17,27.22 111.75,26.79 111.75,22.56
VCCIN_VCC on TOP: 99.64,26.79 100.45,26.79 101.49,25.74 101.49,24.95 101.99,24.45 101.99,23.23 102.34,22.89 103.17,22.89 103.17,22.69 103.17,22.69 102.11,22.69 101.77,23.04 101.28,23.04 101.27,23.03 100.9,23.41 100.9,24.6 100.45,25.05 99.72,25.05 99.62,25.15 99.62,26.77
VDDQ_SW on BOTTOM: 46.35,80.79 46.3,80.74 45.46,80.74 45.41,80.69 45.41,80.57 45.46,80.52 46.45,80.52 46.73,80.24 47.8,80.24 48.92,79.12 51.1,79.12 51.31,78.92 51.31,78.43 51.43,78.31 52.63,78.31 53.85,79.52 53.85,81.79 53.69,81.94 49.5,81.94 48.36,80.79
VDDQSNS on BOTTOM: 46.68,78.76 45.41,78.76 45.31,78.66 45.31,76.22 45.36,76.17 46.18,76.17 46.38,76.38 46.38,76.68 46.63,76.93 47.39,76.93 47.5,77.04 47.5,77.95
1P8VSX on TOP: 187.46,26.52 186.97,26.52 186.86,26.4 186.86,23.26 186.97,23.15 187.15,23.15 187.24,23.24 187.24,23.7 187.56,24.01 187.56,26.42
+PLLVDD on TOP: 138.52,66.49 140.97,66.49 141.22,66.24 141.22,65.48 140.97,65.22 138.17,65.22 138.05,65.35 138.05,66.02
+PLLVDD on TOP: 133.73,59.38 134.87,59.38 135.13,59.64 135.76,59.64 135.89,59.51 135.89,58.24 135.76,58.11 135,58.11 134.75,57.86 133.86,57.86 133.6,58.11 133.6,59.26
+VADP on TOP: 20.19,73.96 20.32,73.84 20.32,72.67 20.37,72.62 20.37,72.01 20.52,71.85 21.61,71.85 21.97,71.5 21.97,69.75 21.59,69.36 21.59,68.7 21.24,68.35 21.24,68.1 21.03,67.89 19.76,67.89 19.61,68.04 19.61,68.43 19.51,68.53 18.67,68.53 18.54,68.65 18.54,72.19 17.2,73.53 15.92,73.53 15.73,73.72 15.73,75.98 15.92,76.17 19.41,76.17 19.51,76.07 19.51,75.46 20.19,74.78
+VADP on BOTTOM: 19.05,69.29 22.1,69.29 22.22,69.42 22.22,71.45 22.02,71.65 20.24,71.65 19.94,71.96 19.94,72.59 19.81,72.72 18.67,72.72 18.54,72.59 18.54,69.8
+VADP_CONN on TOP: 18.16,81.3 18.16,78.18 18.54,77.79 19.1,77.79 19.33,77.56 19.33,76.68 19.11,76.46 15.48,76.46 15.43,76.51 15.43,77.04 15.37,77.1 15.37,77.92 15.64,78.2 15.64,81.38 15.75,81.48 17.98,81.48
+VCON_IN on BOTTOM: 48.86,36.53 49,36.53 49.18,36.35 51.5,36.35 51.56,36.29 51.56,35.58 51.52,35.54 50.34,35.54 50.07,35.81 49.12,35.81 48.73,36.2 48.73,36.41
+VGA_CORE on TOP: outline of 121 points within 126.93,36.15 156.31,75.95
+VGA_CORE on BOTTOM: 135.74,36.3 135.35,36.69 135.35,44.04 135.04,44.35 132.71,44.35 125.98,51.09 125.98,63.9 128.08,66 128.08,72.64 128.96,73.52 134.57,73.52 135.04,74 138.42,74 139.43,75.01 140.78,75.01 141.01,75.24 155.86,75.24 156.17,74.94 156.17,66.69 155.15,65.67 150.6,65.67 149.66,64.73 149.66,64.65 149.43,64.42 138.21,64.42 138.09,64.54 131.93,64.54 130.91,63.52 130.91,59.88 130.37,59.35 130.37,53.12 135.12,48.37 143.34,48.37 143.69,48.02 143.69,36.57 143.42,36.3
+VGA_CORE on ART03: 156.39,75.04 156.39,67.09 154.97,65.67 143.89,65.67 143.55,66.01 143.55,74.8 143.93,75.17 156.26,75.17
+VGA_CORE on PWR04: 156.37,75.44 156.51,75.3 156.51,66.59 155.63,65.71 144.82,65.71 143.9,64.79 143.9,53.52 144.86,52.56 144.86,37.57 144.12,36.82 131.23,36.82 130.64,37.41 130.64,37.42 130.32,37.74 130.32,50.64 128.09,52.87 128.09,74.75 133.33,80 155.44,80 156.37,79.07
+VGA_CORE on ART05: 156.37,75.44 156.51,75.3 156.51,66.59 155.63,65.71 140.94,65.71 138.3,63.07 138.3,50.24 138.94,49.6 139.32,49.6 141.22,47.7 141.22,39.82 140.52,39.13 137.02,39.13 136.09,40.05 136.09,41.78 132.03,45.84 130.58,45.84 129.16,47.27 129.16,71.13 138.02,80 155.44,80 156.37,79.07
+VGA_CORE on ART06: 142.07,75.59 151.56,75.59 151.76,75.38 151.76,73.48 156.35,68.9 156.35,67.08 155.13,65.86 141.01,65.86 139.77,67.1 139.77,74.74 140.06,75.02 141.5,75.02
+VPVDD on TOP: 171.7,23.44 172.42,23.44 173.02,22.84 173.02,21.05 173.68,20.39 174.5,20.39 174.8,20.09 174.8,19.07 174.65,18.92 172.88,18.92 171.91,19.89 171.91,19.89 171.55,20.25 171.55,22.78 171.65,22.88 171.65,23.39
+VSYS on TOP: outline of 141 points within 35.35,4.98 179.86,81.96 ; 8 cut-outs
+VSYS on TOP: 18.19,69.95 16.56,69.95 16.33,69.72 16.33,67.58 16.43,67.49 18.17,67.49 18.25,67.57 18.25,69.9
+VSYS on BOTTOM: 37.69,80.07 35.77,80.07 35.61,80.24 35.61,81.96 36.14,82.5 41.12,82.5 42.77,80.85 43.43,80.85 43.48,80.79 43.48,80.44 43.58,80.34 46.33,80.34 46.43,80.24 46.43,79.93 46.33,79.83 44.19,79.83 43.86,79.5 38.26,79.5
+VSYS on BOTTOM: 53.08,55.19 53.24,55.04 53.24,53.16 53.11,53.03 51.05,53.03 50.42,53.67 50.42,54.48 50.32,54.58 50.32,54.66 50.26,54.71 49.27,54.71 49.22,54.66 49.22,54.18 49.17,54.12 48,54.12 47.93,54.2 47.93,54.52 48,54.59 48,55.05 48.14,55.19
+VSYS on BOTTOM: 71.53,31.47 70.76,30.71 70.76,29.79 70.91,29.64 71.37,29.64 71.58,29.84 71.58,29.93 72.08,30.44 72.98,30.44 73.07,30.53 73.07,31.37 72.97,31.47
+VSYS on BOTTOM: 80.64,21.95 75.52,21.95 75.41,21.83 75.41,15.12 75.48,15.05 77.81,15.05 78.46,15.69 81.01,15.69 81.03,15.72 81.03,16.32 80.72,16.63 80.72,21.87
+VSYS on BOTTOM: 162.69,44.02 162.81,43.89 162.81,42.24 162.69,42.11 161.92,42.11 161.29,42.75 160.91,42.75 160.65,42.49 160.65,40.33 160.91,40.08 160.91,36.27 161.67,35.51 161.67,32.56 161.4,32.29 157.82,32.29 157.67,32.44 157.67,34.82 158.62,35.76 158.62,43.63 159,44.02
+VSYS on PWR04: 17.18,71.78 16.16,70.76 16.16,67.81 16.47,67.5 22.45,67.5 22.77,67.82 22.77,71.49 23.86,72.58 23.86,79.18 25.11,80.44 38.25,80.44 38.35,80.54 38.35,83.64 37.49,84.5 35.66,84.5 35.66,84.5 19.7,84.5 17.18,81.98
AUD_GND on TOP: 185.3,28.85 185.3,26.36 185.27,26.34 183.69,26.34 183.64,26.39 183.64,26.9 183.65,26.91 184.04,26.91 184.14,27 184.14,27.15 184.4,27.42 184.4,28.62 184.71,28.93 185.21,28.93
AUD_GND on BOTTOM: 183.14,38.36 184.86,38.36 185.3,37.92 185.3,35.89 185.06,35.65 185.06,34.52 185.3,34.28 185.3,26.38 185.27,26.34 182.73,26.34 182.43,26.04 176.18,26.04 176.15,26.07 176.15,30.97 175.91,31.21 174.6,31.21 174.55,31.26 174.55,33.91 174.67,34.04 181.28,34.04 182.57,35.33 182.57,37.79
AUD_GND on GND02: 183.14,38.36 184.86,38.36 185.3,37.92 185.3,29.73 185.3,29.73 185.3,26.37 185.28,26.34 182.73,26.34 182.43,26.04 176.18,26.04 176.15,26.07 176.15,30.97 175.91,31.21 174.6,31.21 174.55,31.26 174.55,33.8 174.78,34.04 181.28,34.04 182.57,35.33 182.57,37.79
AUD_GND on ART03: 174.55,32.16 174.55,33.8 174.78,34.04 181.28,34.04 182.57,35.33 182.57,37.79 183.14,38.36 184.86,38.36 185.3,37.92 185.3,26.36 185.28,26.34 182.73,26.34 182.43,26.04 177.46,26.04 176.16,27.35 176.16,31.25 177.43,32.52 177.49,32.52 177.49,32.65 175.7,32.65 175.09,32.03 174.67,32.03
AUD_GND on PWR04: 183.14,38.36 184.86,38.36 185.3,37.92 185.3,26.37 185.27,26.34 183.89,26.34 183.89,28.43 185.18,29.71 185.18,35.84 184.85,36.17 183.03,36.17 182.68,35.82 182.68,34.75 181.77,33.84 180.1,33.84 179.45,33.2 179.45,26.17 179.32,26.04 176.18,26.04 176.15,26.07 176.15,30.97 175.91,31.21 174.6,31.21 174.55,31.26 174.55,33.8 174.78,34.04 181.28,34.04 182.57,35.33 182.57,37.79
AUD_GND on ART05: 183.14,38.36 184.86,38.36 185.3,37.92 185.3,26.36 185.28,26.34 182.73,26.34 182.43,26.04 176.18,26.04 176.15,26.07 176.15,30.97 175.91,31.21 174.6,31.21 174.55,31.26 174.55,33.8 174.78,34.04 181.28,34.04 182.57,35.33 182.57,37.79
AUD_GND on ART06: 183.14,38.36 184.86,38.36 185.3,37.92 185.3,26.36 185.28,26.34 184.18,26.34 184.05,26.48 184.05,27.27 184.26,27.48 184.26,28.74 185.2,29.69 185.2,37.59 184.97,37.83 183.37,37.83 182.69,37.14 182.69,34.77 181.76,33.84 180.33,33.84 179.45,32.96 179.45,26.16 179.33,26.04 176.18,26.04 176.15,26.07 176.15,30.97 175.91,31.21 174.6,31.21 174.55,31.26 174.55,33.8 174.78,34.04 181.28,34.04 182.57,35.33 182.57,37.79
AUD_GND on GND07: 183.14,38.36 184.86,38.36 185.3,37.92 185.3,26.36 185.28,26.34 182.73,26.34 182.43,26.04 176.18,26.04 176.15,26.07 176.15,30.97 175.91,31.21 174.6,31.21 174.55,31.26 174.55,33.8 174.78,34.04 181.28,34.04 182.57,35.33 182.57,37.79
CHG_SW1 on BOTTOM: 59.07,17.49 55.87,17.49 55.8,17.42 55.8,13.18 56.15,12.82 64.38,12.82 64.97,13.41 64.97,18.36 64.62,18.71 60.3,18.71
CHG_SW2 on BOTTOM: 74.31,17.21 74.92,17.21 74.95,17.19 74.95,14.88 75.29,14.54 77.33,14.54 77.49,14.39 77.49,12.13 77.38,12.02 68.85,12.02 68.2,12.67 68.2,18.36 68.49,18.65 72.88,18.65
CORE+PLLVDD on TOP: 144.32,67.88 144.52,68.08 144.69,68.08 145.29,68.68 145.83,68.68 146.03,68.47 146.03,67.79 145.98,67.74 145.08,67.74 144.93,67.58 144.93,67.18 144.88,67.13 144.42,67.13 144.32,67.23
DC_JACK_IN on TOP: 11.52,79.32 10.21,79.32 9.75,78.86 9.75,77.29 10.06,76.98 11.33,76.98 11.68,76.63 11.68,73.1 11.76,73.02 13.38,73.02 13.59,73.23 13.59,74.12 13.88,74.42 15.12,74.42 15.28,74.58 15.28,76.03 15.15,76.17 13.69,76.17 13.46,76.4 13.46,77.04 14.5,78.08 14.86,78.08 14.98,78.2 14.98,81.35 14.86,81.48 13.68,81.48
DC_JACK_IN on BOTTOM: 12.95,79.32 9.52,79.32 9.4,79.19 9.4,76.91 9.65,76.65 11.3,76.65 11.68,76.27 11.68,73.23 11.81,73.1 14.86,73.1 15.44,73.68 15.44,75.87 15.19,76.12 13.87,76.12 13.33,76.65 13.33,76.78 13.08,77.04 13.08,79.19
DC_JACK_IN on ART03: 10.21,79.32 9.75,78.86 9.75,77.29 10.06,76.98 11.33,76.98 11.57,76.74 11.57,73.35 11.89,73.02 15.26,73.02 15.72,73.49 15.72,79.12 15.52,79.32
DC_JACK_IN on PWR04, ART05: 10.13,79.58 16.39,79.58 16.78,79.18 16.78,72.54 16.12,71.88 12.02,71.88 11.52,72.38 11.52,76.12 11.01,76.64 10.2,76.64 9.76,77.08 9.76,79.21
DC_JACK_IN on ART06: 10.13,79.58 16.39,79.58 16.78,79.18 16.78,75.02 15.7,73.94 15.7,72.36 15.22,71.88 12.02,71.88 11.52,72.38 11.52,76.12 11.01,76.64 10.2,76.64 9.76,77.08 9.76,79.21
DDR_1P8A_SW on BOTTOM: 46.94,81.81 47.04,81.71 47.7,81.71 47.93,81.94 47.93,84.94 47.88,84.99 46.23,84.99 46.2,84.96 46.2,84.3 46.94,83.56
FB_PLLAVDD on TOP: 152.93,64.08 152.78,64.08 152.65,64.21 152.65,65 152.91,65.25 153.59,65.25 153.65,65.19 153.65,64.86 154.01,64.5 154.01,64.13 153.43,63.55 153.11,63.55 153.08,63.57 153.08,63.93
FB_PLLAVDD on BOTTOM: 157.94,87.59 158.97,87.59 159.08,87.47 159.08,86.89 158.95,86.76 158.95,84.45 158.84,84.35 157.84,84.35 157.81,84.38 157.81,87.47
FB_PLLAVDD on ART06: 152.97,63.79 152.77,63.98 152.77,65.47 152.91,65.61 155.45,65.61 156.72,66.88 156.72,66.88 156.72,68.65 156.73,68.65 156.73,68.78 156.22,69.29 156.21,69.29 152.14,73.35 152.14,84.91 153.29,86.05 159,86.05 159.13,85.93 159.13,84.27 157.73,82.88 157.73,71.7 159.38,70.05 159.38,64.97 159.35,64.94 158.27,64.94 158.25,64.92 156.46,64.92 156.14,64.6 154.57,64.6 153.76,63.79
HGNDA on TOP: 182.03,27.06 182.07,27.02 182.07,26.18 181.86,25.98 181.59,25.98 181.48,26.09 181.48,26.29 181.48,26.29 181.48,26.48 181.45,26.51 181.18,26.51 180.65,25.98 180.13,25.98 180.03,26.08 180.03,27.1 180.08,27.15 180.33,27.15 180.43,27.06
HGNDA on ART06: 183.58,37.64 184.81,37.64 184.96,37.49 184.96,36.5 184.44,35.98 184.44,29.64 183.16,28.36 183.16,26.37 182.75,25.96 180.01,25.96 179.85,26.13 179.85,30.89 180.49,31.53 180.49,33.3 180.84,33.65 182.32,33.65 182.9,34.22 182.9,36.96
HGNDB on TOP: 181.88,28.51 182.01,28.37 182.01,27.39 181.94,27.32 181.5,27.32 181.46,27.35 181.46,27.71 181.36,27.81 181.17,27.81 180.72,27.35 180.08,27.35 180.03,27.4 180.03,28.45 180.08,28.5 180.74,28.5 180.74,28.51
HGNDB on PWR04: 179.87,27.08 179.7,27.25 179.7,32.73 180.38,33.4 180.7,33.4 180.85,33.55 182.24,33.55 182.93,34.25 182.93,35.46 183.1,35.63 184.87,35.63 184.99,35.5 184.99,30.19 183.09,28.28 183.09,27.39 182.78,27.08
SPKL_N1 on BOTTOM: 184.71,42.04 186.64,42.04 186.79,42.19 186.79,42.64 186.58,42.86 184.71,42.86 184.61,42.75 184.61,42.14
SPKR_P1 on BOTTOM: 184.71,40.37 185.92,40.37 186.08,40.21 186.08,39.71 185.93,39.55 184.66,39.55 184.55,39.65 184.55,40.21
VGA_CORE1_IN on BOTTOM (solid shape): 152.65,48.87 153.17,48.87 153.17,49.5 153.92,49.5 153.92,48.87 154.44,48.87 154.44,49.5 154.91,49.5 154.91,47.59 150.91,47.59 150.91,48.03 151.92,48.03 151.92,49.5 152.65,49.5
VGA_CORE1_IN on TOP: 156.67,47.35 156.99,47.67 158.24,47.67 158.91,47.01 158.91,45.05 158.73,44.88 156.71,44.88 156.67,44.92
VGA_CORE1_IN on BOTTOM: 171.07,39.95 170.94,40.08 170.94,40.97 171.32,41.35 171.32,42.36 172.21,43.25 172.21,44.78 170.94,46.05 167.99,46.05 167.94,46.1 167.13,46.1 167.08,46.05 165.73,46.05 165.48,45.79 163.96,45.79 162.81,44.65 159.89,44.65 159.66,44.88 156.51,44.88 156.2,45.19 156.2,47.05 155.7,47.56 150.97,47.56 150.87,47.66 150.87,48.03 150.92,48.08 151.74,48.08 151.91,48.25 151.91,49.5 152.32,49.91 157.96,49.91 160.92,46.95 164.48,46.95 165.22,47.69 171.27,47.69 171.71,47.25 172.37,47.25 173.86,45.75 173.86,43 172.46,41.6 172.46,40.46 171.96,39.95
VGA_CORE2_IN on BOTTOM (solid shape): 154.86,36.09 153.85,36.09 153.85,34.62 153.12,34.62 153.12,35.25 152.6,35.25 152.6,34.62 151.85,34.62 151.85,35.25 151.33,35.25 151.33,34.62 150.86,34.62 150.86,36.53 154.86,36.53
VGA_CORE2_IN on TOP: 159.23,35.91 159.1,35.79 155.82,35.79 155.78,35.82 155.78,38.84 155.99,39.05 159.01,39.05 159.23,38.82
VGA_CORE2_IN on BOTTOM: 155.4,37.11 154.94,36.65 150.78,36.65 150.52,36.39 150.52,34.24 151.01,33.75 155.95,33.75 158.14,35.94 158.14,38.99 158.07,39.06 155.62,39.06 155.4,38.83
VGA_CORE_PHASE1 on BOTTOM: 146.3,41.93 146.3,48.69 146.4,48.79 149.4,48.79 149.86,48.33 149.86,47.37 150.26,46.96 154.84,46.96 155.09,46.71 155.09,44.42 154.89,44.22 150.11,44.22 149.65,43.76 149.65,41.93 149.6,41.88 146.35,41.88
VGA_CORE_PHASE2 on BOTTOM: 146.3,36.58 146.3,41.42 146.35,41.48 149.86,41.48 150.01,41.32 150.01,40 150.11,39.9 154.79,39.9 154.94,39.75 154.94,37.31 154.79,37.16 150.37,37.16 150.36,37.16 150.3,37.16 149.49,36.35 146.53,36.35
N22799047 on BOTTOM: 164.92,88.12 167.29,88.12 167.66,88.49 168.45,88.49 168.76,88.19 168.76,86.35 168.61,86.2 164.22,86.2 164.04,86.39 164.04,87.23
N28274141 on BOTTOM: 71.96,29.83 74.28,29.83 74.55,29.56 75.05,29.56 75.11,29.5 75.11,27.46 75.3,27.27 75.3,27.08 75.29,27.06 74.48,27.06 74.47,27.08 74.47,28.83 74.23,29.07 71.97,29.07 71.92,29.12 71.92,29.79
N28767371 on BOTTOM: 169.67,57.22 170.69,57.22 170.79,57.12 170.79,52.6 170.64,52.45 170.08,52.45 169.92,52.3 169.92,51.72 169.85,51.65 169.55,51.65 169.47,51.74 169.47,57.02
N29341220 on BOTTOM: 40.69,65.5 40.54,65.35 39.22,65.35 39.16,65.3 39.16,64.79 39.32,64.64 41.7,64.64 41.86,64.79 41.86,65.45 41.81,65.5
N29341270 on BOTTOM: 42.01,70.23 41.2,70.23 41.15,70.18 41.15,68.45 41.35,68.25 43.08,68.25 43.18,68.35 43.18,69.36 43.33,69.52 43.33,69.77 43.28,69.82 42.42,69.82
N31718510 on BOTTOM: 49.07,65.61 50.7,65.61 50.8,65.71 50.8,66.42 50.75,66.47 49.07,66.47 48.97,66.37 48.97,65.71
N32261981 on BOTTOM: 129.69,75.94 134.11,75.94 134.52,75.54 134.52,74.32 134.36,74.17 129.49,74.17 129.33,74.32 129.33,75.59
N33091607 on BOTTOM: 129.28,85.8 131.7,85.8 131.82,85.67 131.82,84.53 131.7,84.4 129.16,84.4 129.03,84.53 129.03,85.54
N38465677 on TOP: 18.8,82.24 19.96,82.24 20.03,82.16 20.03,78.27 19.9,78.14 18.76,78.14 18.69,78.2 18.69,82.13
N39761277 on BOTTOM: 131.18,93.79 131.3,93.66 131.3,92.87 131.56,92.6 131.56,91.81 131.42,91.67 130.85,91.67 130.21,92.3 130.21,93.71 130.29,93.79
N40385596 on BOTTOM: 56.06,23.27 58.98,23.27 59.22,23.04 59.22,18.4 59.03,18.21 54.57,18.21 54.19,17.83 52.41,17.83 52.37,17.87 52.37,19.37 52.94,19.95 52.94,21.25 52.91,21.28 52.39,21.28 52.37,21.3 52.37,24.63 52.47,24.74 54.59,24.74
N40874129 on BOTTOM: 40.93,61.15 40.93,60.41 40.91,60.39 40.66,60.39 40.65,60.4 40.65,61.41 40.26,61.8 39.93,61.8 39.83,61.9 39.83,63.12 39.93,63.22 40.74,63.22 40.99,62.96 41.96,62.96 42.06,62.86 42.06,62 41.96,61.9 41.68,61.9
N40903561 on TOP: 20.37,15.97 20.37,13.89 20.78,13.48 20.78,12.93 20.83,12.88 21.08,12.88 21.23,12.72 21.23,12.47 21.33,12.37 21.57,12.37 21.59,12.39 21.59,14.23 21.69,14.33 21.69,14.55 21.89,14.75 21.89,16.18 21.84,16.23 20.62,16.23
N41026409 on TOP: 62.61,46.3 65.02,46.3 65.38,45.95 65.38,44.73 65.3,44.65 62.66,44.65 62.57,44.74 62.57,46.26
N41496656 on BOTTOM: 19.94,67.92 19.3,67.28 19.3,66.32 19.4,66.22 21.03,66.22 21.13,66.32 21.13,66.93 21.33,67.13 21.59,67.13 22.48,68.02 22.48,68.78 22.35,68.91 20.06,68.91 19.94,68.78
N42059320 on BOTTOM: 32.76,63.07 32.64,62.94 29.97,62.94 29.84,63.07 29.84,65.73 29.97,65.86 31.24,65.86 31.6,65.5 31.6,64.89 31.85,64.64 32.76,64.64

Small or netless copper shapes (teardrops, artwork), in the pictures only: 93 on TOP, 14 on BOTTOM

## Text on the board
Ref Des/Silkscreen Bottom: JWLAN
User.Comments: CR_1340_2 | CR_1340_1
Ref Des/Assembly Top: U*
Ref Des/Silkscreen Top: NB8511_PCB_MB_V4
DEVICE_TYPE_BOTTOM: dia 2.80 | dia 2.10 | 2.60 | dia 3.50
User.8: dia 2.80 | dia 2.10 | 2.60 | dia 3.50
User.38: FIGURE | SIZE | 8.0 | 10.0 | 21.654 | 27.559 | 110.236 | 137.795 | 23.622 | 43.307 | 57.087 | 62.992 | 82.68 | 49.213x27.559 | 59.06x19.69 | 62.992x31.496 | 74.8x39.37 | 74.803x23.622 | 74.803x31.496 | 78.74x27.559 | 94.488x43.307 | 102.362x31.496 | 118.11x23.622 | 33.465x19.685 | 98.425x86.614 | DRILL CHART: TOP to BOTTOM | ALL UNITS ARE IN MILS | PLATED | NON-PLATED | QTY | 3872 | 1394 | 19 | 9 | 5 | 1 | 2
User.45: REVC | LPID_5366
